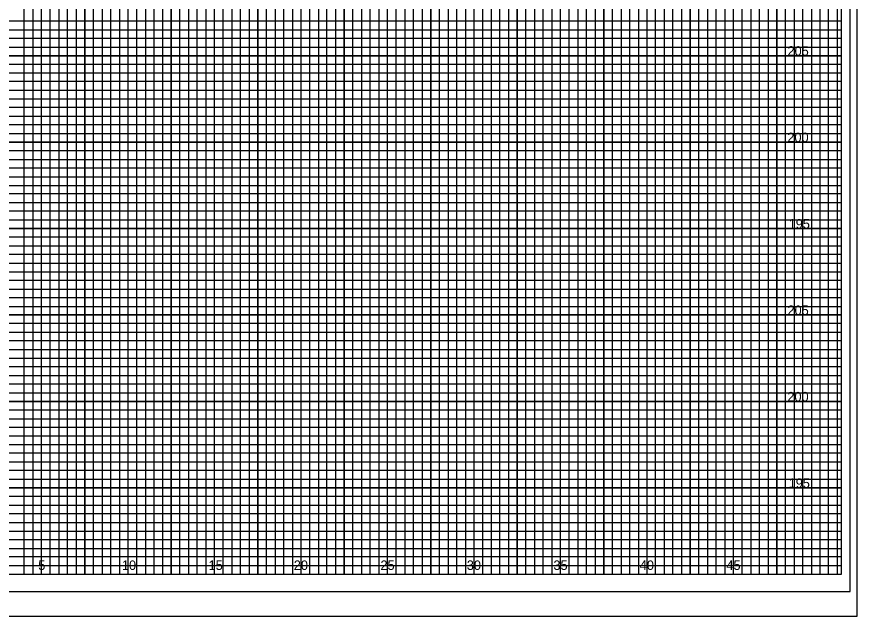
# Model space of a CAD drawing. Extents: x -4 to 103, y -2 to 209.
# Drawn here: x 54.82 to 103.4, y 68.4 to 103.08 of the extents above; entities that cross this region are included whole.
import ezdxf

# ---------------------------------------------------------------- set-up
doc = ezdxf.new("R2010")
doc.units = 0
for name, color, linetype in [('Exist XS Ground Line', 7, 'Continuous'), ('Old_Level_10', 7, 'Continuous'), ('Old_Level_16', 7, 'Continuous'), ('Old_Level_3', 7, 'Continuous'), ('Old_Level_5', 7, 'Continuous'), ('Old_Level_8', 7, 'Continuous'), ('Prop XS Finish Grade Earthwork', 7, 'Continuous'), ('Prop XS Finish Grade Pavement', 7, 'Continuous'), ('Prop XS SE Text', 7, 'Continuous')]:
    doc.layers.add(name, color=color, linetype=linetype)

msp = doc.modelspace()

# ---------------------------------------------------------------- linework, layer by layer
at = {"layer": 'Exist XS Ground Line'}
msp.add_lwpolyline([(103, 136.825), (-2.8, 136.825), (-2.8, 69.825), (103, 69.825)], close=True, dxfattribs=at)
at = {"layer": 'Old_Level_10'}
for p, q in [((56.25, 70.825), (56.25, 135.825)), ((58.75, 70.825), (58.75, 135.825)), ((61.25, 70.825), (61.25, 135.825)), ((63.75, 70.825), (63.75, 135.825)), ((66.25, 70.825), (66.25, 135.825)), ((68.75, 70.825), (68.75, 135.825)), ((71.25, 70.825), (71.25, 135.825)), ((73.75, 70.825), (73.75, 135.825)), ((91.25, 70.825), (91.25, 134.25)), ((93.75, 70.825), (93.75, 134.25)), ((96.25, 70.825), (96.25, 134.25)), ((98.75, 70.825), (98.75, 134.25)), ((101.25, 70.825), (101.25, 134.25)), ((76.25, 70.825), (76.25, 132.825)), ((78.75, 70.825), (78.75, 132.825)), ((81.25, 70.825), (81.25, 132.825)), ((83.75, 70.825), (83.75, 132.825)), ((86.25, 70.825), (86.25, 132.825)), ((88.75, 70.825), (88.75, 132.825)), ((0, 100.825), (102.5, 100.825)), ((0, 98.325), (102.5, 98.325)), ((0, 95.825), (102.5, 95.825)), ((0, 93.325), (102.5, 93.325)), ((0, 90.825), (102.5, 90.825)), ((0, 88.325), (102.5, 88.325)), ((0, 85.825), (102.5, 85.825)), ((0, 83.325), (102.5, 83.325)), ((0, 80.825), (102.5, 80.825)), ((0, 78.325), (102.5, 78.325)), ((0, 75.825), (102.5, 75.825)), ((0, 73.325), (102.5, 73.325))]:
    msp.add_line(p, q, dxfattribs=at)
at = {"layer": 'Old_Level_3'}
msp.add_line((-3.5, 68.4), (103.4, 68.4), dxfattribs=at)
at = {"layer": 'Old_Level_5'}
msp.add_lwpolyline([(103.4, 138.225), (-3.5, 138.225), (-3.5, 68.4), (103.4, 68.4)], close=True, dxfattribs=at)
at = {"layer": 'Old_Level_8'}
for points in [[(56.25, 70.825), (56.25, 135.825)], [(58.75, 135.825), (58.75, 70.825), (61.25, 70.825), (61.25, 135.825)], [(63.75, 135.825), (63.75, 70.825), (66.25, 70.825), (66.25, 135.825)], [(68.75, 135.825), (68.75, 70.825), (71.25, 70.825), (71.25, 135.825)], [(73.75, 135.825), (73.75, 70.825), (76.25, 70.825), (76.25, 132.825)], [(88.75, 132.825), (88.75, 70.825), (91.25, 70.825), (91.25, 134.25)], [(93.75, 134.25), (93.75, 70.825), (96.25, 70.825), (96.25, 134.25)], [(98.75, 134.25), (98.75, 70.825), (101.25, 70.825), (101.25, 134.25)], [(78.75, 132.825), (78.75, 70.825), (81.25, 70.825), (81.25, 132.825)], [(83.75, 132.825), (83.75, 70.825), (86.25, 70.825), (86.25, 132.825)], [(0, 98.325), (102.5, 98.325), (102.5, 100.825), (0, 100.825)], [(0, 93.325), (102.5, 93.325), (102.5, 95.825), (0, 95.825)], [(0, 88.325), (102.5, 88.325), (102.5, 90.825), (0, 90.825)], [(0, 83.325), (102.5, 83.325), (102.5, 85.825), (0, 85.825)], [(0, 78.325), (102.5, 78.325), (102.5, 80.825), (0, 80.825)], [(0, 73.325), (102.5, 73.325), (102.5, 75.825), (0, 75.825)]]:
    msp.add_lwpolyline(points, dxfattribs=at)
at = {"layer": 'Prop XS Finish Grade Earthwork'}
for points in [[(54.75, 70.825), (55.25, 70.825), (55.25, 135.825)], [(55.75, 135.825), (55.75, 70.825), (56.75, 70.825), (56.75, 135.825)], [(57.25, 135.825), (57.25, 70.825), (57.75, 70.825), (57.75, 135.825)], [(58.25, 135.825), (58.25, 70.825), (59.25, 70.825), (59.25, 135.825)], [(59.75, 135.825), (59.75, 70.825), (60.25, 70.825), (60.25, 135.825)], [(60.75, 135.825), (60.75, 70.825), (61.75, 70.825), (61.75, 135.825)], [(62.25, 135.825), (62.25, 70.825), (62.75, 70.825), (62.75, 135.825)], [(63.25, 135.825), (63.25, 70.825), (64.25, 70.825), (64.25, 135.825)], [(64.75, 135.825), (64.75, 70.825), (65.25, 70.825), (65.25, 135.825)], [(65.75, 135.825), (65.75, 70.825), (66.75, 70.825), (66.75, 135.825)], [(67.25, 135.825), (67.25, 70.825), (67.75, 70.825), (67.75, 135.825)], [(68.25, 135.825), (68.25, 70.825), (69.25, 70.825), (69.25, 135.825)], [(69.75, 135.825), (69.75, 70.825), (70.25, 70.825), (70.25, 135.825)], [(70.75, 135.825), (70.75, 70.825), (71.75, 70.825), (71.75, 135.825)], [(72.25, 135.825), (72.25, 70.825), (72.75, 70.825), (72.75, 135.825)], [(73.25, 135.825), (73.25, 70.825), (74.25, 70.825), (74.25, 132.825)], [(89.75, 132.825), (89.75, 70.825), (90.25, 70.825), (90.25, 134.25)], [(90.75, 134.25), (90.75, 70.825), (91.75, 70.825), (91.75, 134.25)], [(92.25, 134.25), (92.25, 70.825), (92.75, 70.825), (92.75, 134.25)], [(93.25, 134.25), (93.25, 70.825), (94.25, 70.825), (94.25, 134.25)], [(94.75, 134.25), (94.75, 70.825), (95.25, 70.825), (95.25, 134.25)], [(95.75, 134.25), (95.75, 70.825), (96.75, 70.825), (96.75, 134.25)], [(97.25, 134.25), (97.25, 70.825), (97.75, 70.825), (97.75, 134.25)], [(98.25, 134.25), (98.25, 70.825), (99.25, 70.825), (99.25, 134.25)], [(99.75, 134.25), (99.75, 70.825), (100.25, 70.825), (100.25, 134.25)], [(100.25, 134.25), (100.75, 134.25), (100.75, 70.825), (101.75, 70.825), (101.75, 134.25), (102.25, 134.25), (102.25, 70.825)], [(74.75, 132.825), (74.75, 70.825), (75.25, 70.825), (75.25, 132.825)], [(75.75, 132.825), (75.75, 70.825), (76.75, 70.825), (76.75, 132.825)], [(77.25, 132.825), (77.25, 70.825), (77.75, 70.825), (77.75, 132.825)], [(78.25, 132.825), (78.25, 70.825), (79.25, 70.825), (79.25, 132.825)], [(79.75, 132.825), (79.75, 70.825), (80.25, 70.825), (80.25, 132.825)], [(80.75, 132.825), (80.75, 70.825), (81.75, 70.825), (81.75, 132.825)], [(82.25, 132.825), (82.25, 70.825), (82.75, 70.825), (82.75, 132.825)], [(83.25, 132.825), (83.25, 70.825), (84.25, 70.825), (84.25, 132.825)], [(84.75, 132.825), (84.75, 70.825), (85.25, 70.825), (85.25, 132.825)], [(85.75, 132.825), (85.75, 70.825), (86.75, 70.825), (86.75, 132.825)], [(87.25, 132.825), (87.25, 70.825), (87.75, 70.825), (87.75, 132.825)], [(88.25, 132.825), (88.25, 70.825), (89.25, 70.825), (89.25, 132.825)], [(0, 102.325), (102.5, 102.325), (102.5, 102.825), (0, 102.825)], [(0, 101.325), (102.5, 101.325), (102.5, 101.825), (0, 101.825)], [(0, 99.825), (102.5, 99.825), (102.5, 100.325), (0, 100.325)], [(0, 98.825), (102.5, 98.825), (102.5, 99.325), (0, 99.325)], [(0, 97.325), (102.5, 97.325), (102.5, 97.825), (0, 97.825)], [(0, 96.325), (102.5, 96.325), (102.5, 96.825), (0, 96.825)], [(0, 94.825), (102.5, 94.825), (102.5, 95.325), (0, 95.325)], [(0, 93.825), (102.5, 93.825), (102.5, 94.325), (0, 94.325)], [(0, 92.325), (102.5, 92.325), (102.5, 92.825), (0, 92.825)], [(0, 91.325), (102.5, 91.325), (102.5, 91.825), (0, 91.825)], [(0, 89.825), (102.5, 89.825), (102.5, 90.325), (0, 90.325)], [(0, 88.825), (102.5, 88.825), (102.5, 89.325), (0, 89.325)], [(0, 87.325), (102.5, 87.325), (102.5, 87.825), (0, 87.825)], [(0, 86.325), (102.5, 86.325), (102.5, 86.825), (0, 86.825)], [(0, 84.825), (102.5, 84.825), (102.5, 85.325), (0, 85.325)], [(0, 83.825), (102.5, 83.825), (102.5, 84.325), (0, 84.325)], [(0, 82.325), (102.5, 82.325), (102.5, 82.825), (0, 82.825)], [(0, 81.325), (102.5, 81.325), (102.5, 81.825), (0, 81.825)], [(0, 79.825), (102.5, 79.825), (102.5, 80.325), (0, 80.325)], [(0, 78.825), (102.5, 78.825), (102.5, 79.325), (0, 79.325)], [(0, 77.325), (102.5, 77.325), (102.5, 77.825), (0, 77.825)], [(0, 76.325), (102.5, 76.325), (102.5, 76.825), (0, 76.825)], [(0, 74.825), (102.5, 74.825), (102.5, 75.325), (0, 75.325)], [(0, 73.825), (102.5, 73.825), (102.5, 74.325), (0, 74.325)], [(0, 72.325), (102.5, 72.325), (102.5, 72.825), (0, 72.825)], [(0, 71.325), (102.5, 71.325), (102.5, 71.825), (0, 71.825)]]:
    msp.add_lwpolyline(points, dxfattribs=at)
at = {"layer": 'Prop XS SE Text'}
msp.add_lwpolyline([(102.5, 135.825), (0, 135.825), (0, 70.825), (102.5, 70.825)], close=True, dxfattribs=at)

# ---------------------------------------------------------------- texts
at = {"layer": 'Old_Level_16'}
for s, p in [('5', (56.057, 71.075)), ('10', (60.897, 71.075)), ('15', (65.906, 71.075)), ('20', (70.831, 71.075)), ('25', (75.84, 71.075)), ('30', (80.831, 71.075)), ('35', (85.84, 71.075)), ('40', (90.831, 71.075)), ('45', (95.84, 71.075))]:
    msp.add_text(s, height=0.55, dxfattribs=at).set_placement(p)
at = {"layer": 'Prop XS Finish Grade Pavement'}
for s, p in [('205', (99.372, 100.825)), ('200', (99.364, 95.825)), ('195', (99.438, 90.825)), ('205', (99.372, 85.825)), ('200', (99.364, 80.825)), ('195', (99.438, 75.825))]:
    msp.add_text(s, height=0.55, dxfattribs=at).set_placement(p)

doc.saveas('drawing.dxf')
